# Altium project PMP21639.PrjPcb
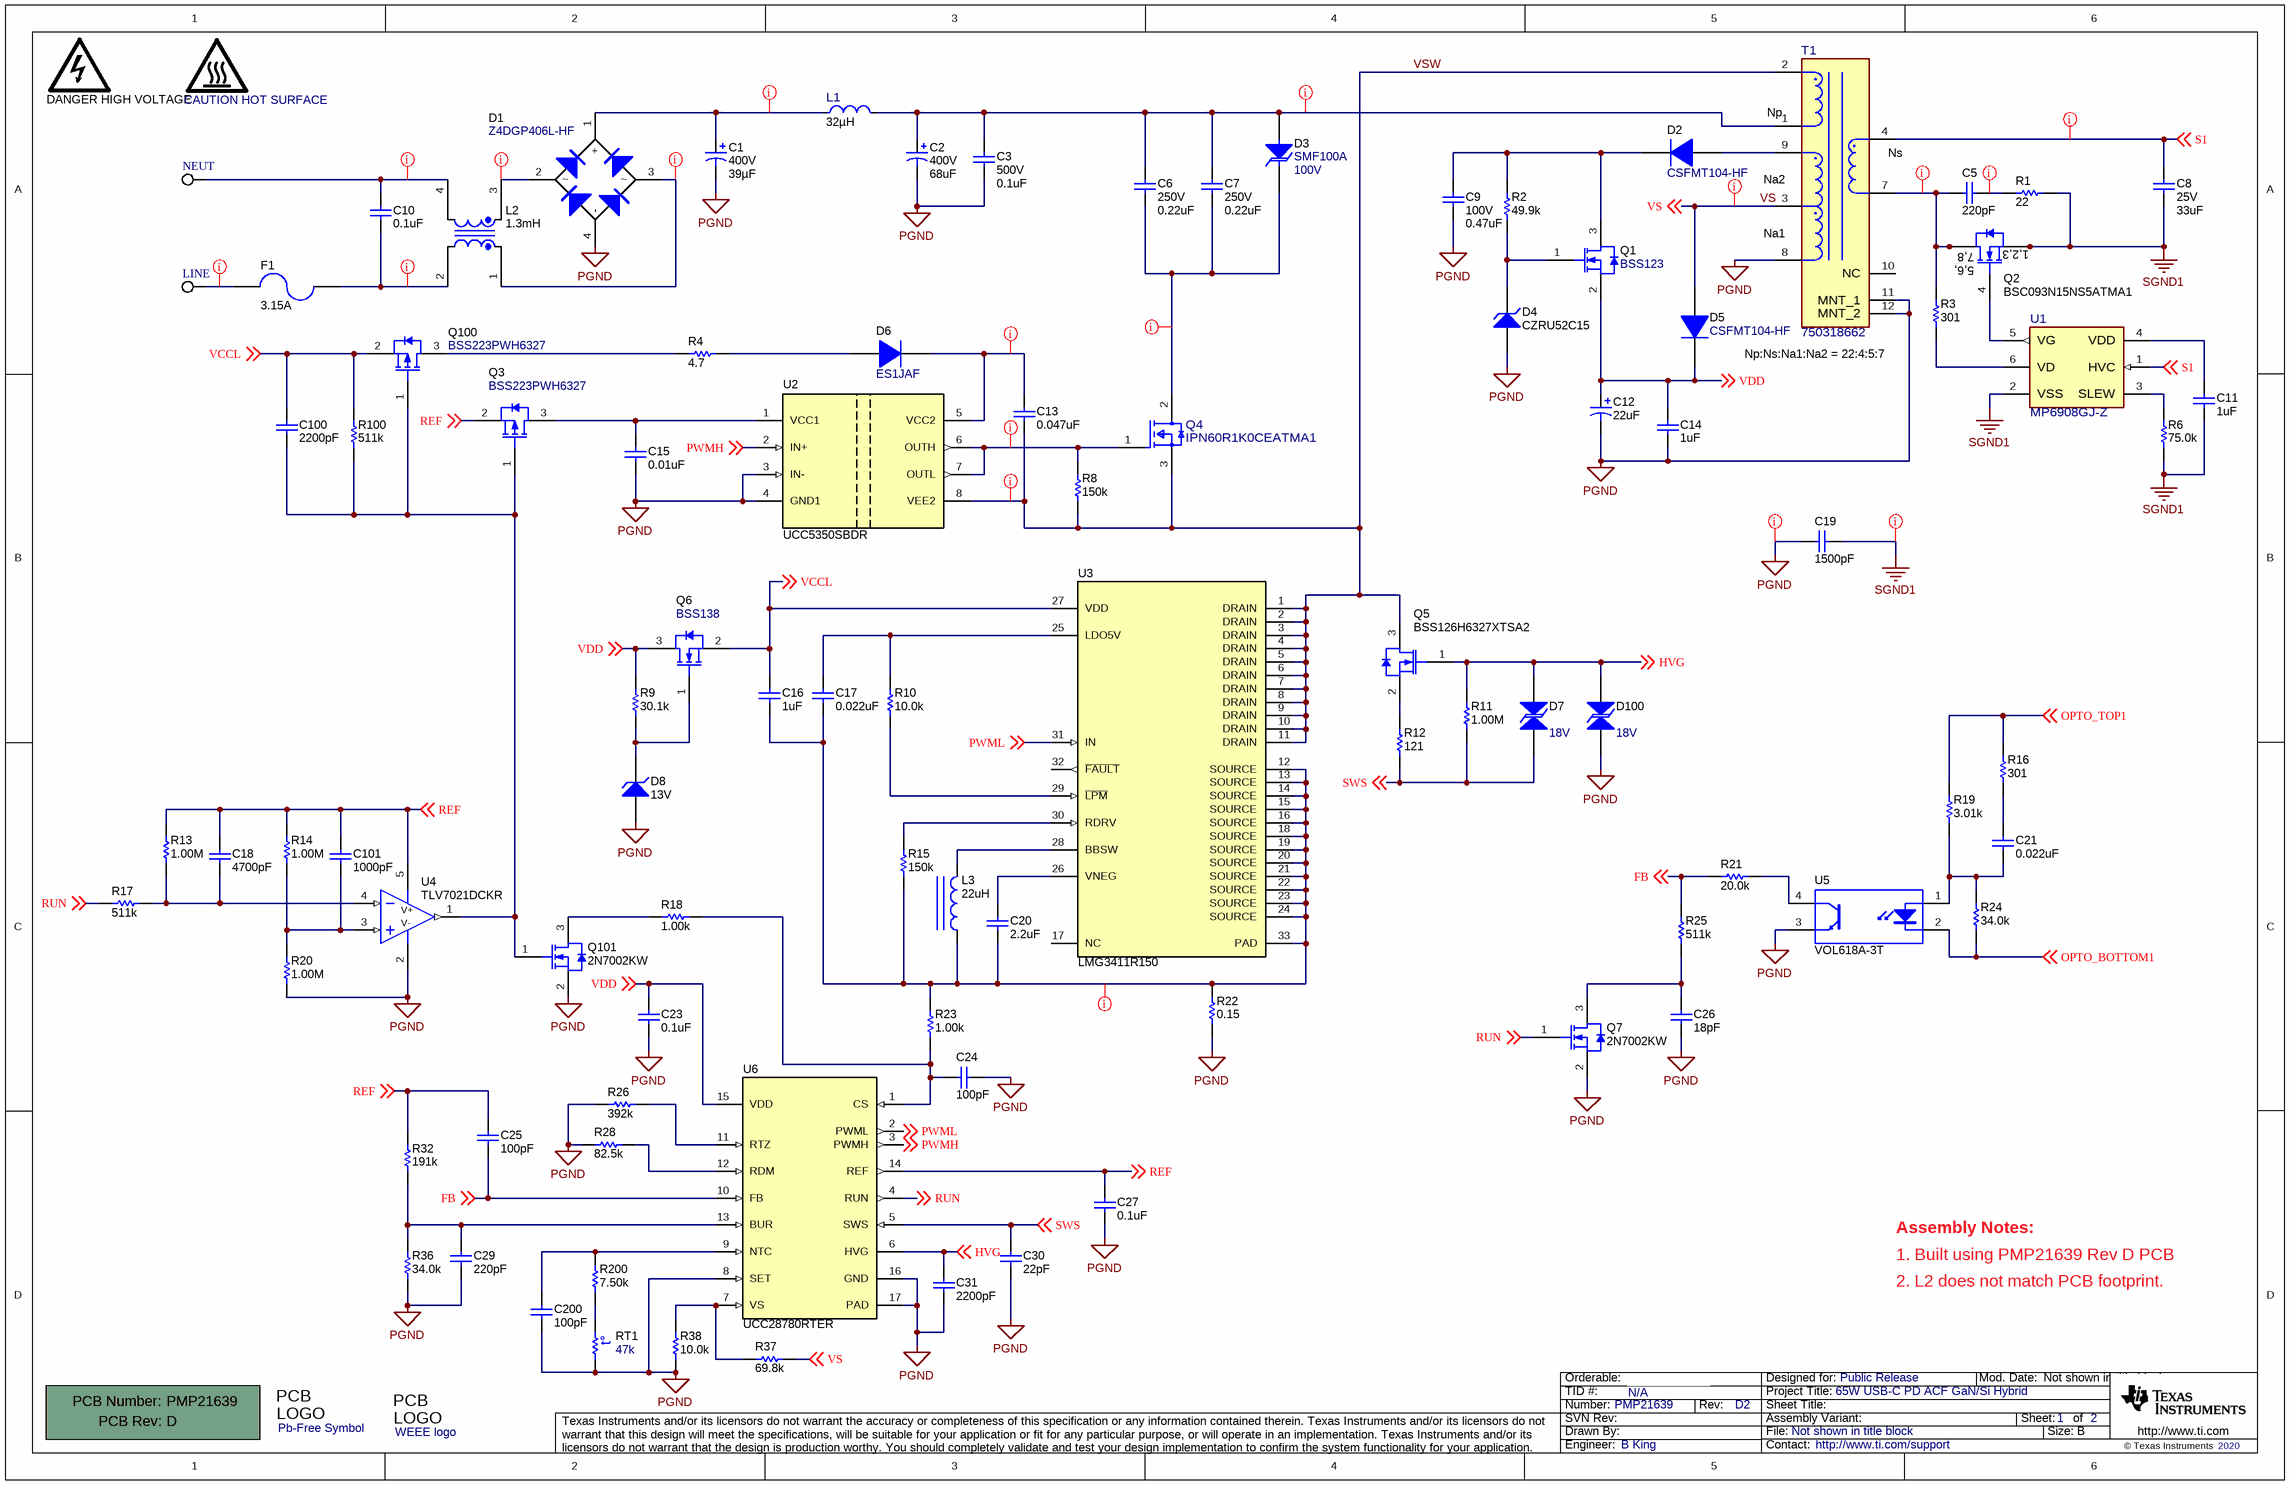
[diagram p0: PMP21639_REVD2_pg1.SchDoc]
TID: N/A; TechSupport: http://www.ti.com/support; SCH_Rev: D2; PRJ_Title: 65W USB-C PD ACF GaN/Si Hybrid; PRJ_Number: PMP21639; PRJ_Engineer: B King; PRJ_Customer: Public Release; PCB_Rev: D; PCB_Layout: B King; CopyrightYear: 2020
2 sheets, 123 parts. Net scope: global (net labels, ports and power ports of the same name join across sheets).
Board file: PMP21639_REVD_PCB.PcbDoc
Sheets:
  PMP21639_REVD2_pg1.SchDoc
  PMP21639_REVD2_pg2.SchDoc

## Sheet PMP21639_REVD2_pg1.SchDoc
size 431 x 279 mm; Date: Not shown in title block; ApprovedBy: Not shown in title block; CheckedBy: Not shown in title block; Author: Not shown in title block; CompanyName: Not shown in title block; Engineer: Not shown in title block; Organization: Not shown in title block; Address1: Not shown in title block; Address2: Not shown in title block; Address3: Not shown in title block; Address4: Not shown in title block; DocumentNumber: 1; Revision: Use project parameter SCH_Rev; SheetNumber: 1; SheetTotal: 2; PageSetup: Record=PageOptions¦CenterHorizontal=True¦CenterVertical=True¦PrintScale=0.48¦XCorrection=1.00¦YCorrection=1.00¦PrintKind=0¦BorderSize=5000000¦LeftOffset=0¦BottomOffset=0¦Orientation=2¦PaperLength=1000¦PaperWidth=1000¦Scale=100¦PaperSource=15¦PrintQuality=-3¦MediaType=1¦DitherType=10¦PrintScaleMode=1¦PaperKind=A5¦PaperIndex=11

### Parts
!PCB1  Printed Circuit Board  (value not drawn)  (mechanical)
C1  VDC_V: 400V  ValueDisplayed: 39µF  [Chemi-Con_1450x2000]  (hidden comment: EKXJ401ELL390MU20S)
C2  VDC_V: 400V  ValueDisplayed: 68uF  [BXW_1800x2000]  (hidden comment: 400BXW68MEFC18X20)
C3  VDC_V: 500V  ValueDisplayed: 0.1uF  [1210_230L]  (hidden comment: C1210W104KCRACTU)
C5  ValueDisplayed: 220pF  [0603S]  (hidden comment: C1608C0G2E221J080AA)
C6  VDC_V: 250V  ValueDisplayed: 0.22uF  [1206L]  (hidden comment: CGA5L3X7T2E224K160AE)
C7  VDC_V: 250V  ValueDisplayed: 0.22uF  [1206L]  (hidden comment: CGA5L3X7T2E224K160AE)
C8  VDC_V: 25V  ValueDisplayed: 33uF  [1206_180L]  (hidden comment: C3216X5R1E336M160AC)
C9  VDC_V: 100V  ValueDisplayed: 0.47uF  [1206_180]  (hidden comment: C3216X7R2A474K160AA)
C10  ValueDisplayed: 0.1uF  [CAPRR1000W60L1250T500H1100]  (hidden comment: BFC242042203)
C11  ValueDisplayed: 1uF  [0603S]  (hidden comment: GRM188R61E105KA12D)
C12  ValueDisplayed: 22uF  [Panasonic_500x1100]  (hidden comment: ECA1HM220)
C13  ValueDisplayed: 0.047uF  [0402S]  (hidden comment: GRM155R71E473KA88D)
C14  ValueDisplayed: 1uF  [0805L]  (hidden comment: C2012X7R1H105K085AC)
C15  ValueDisplayed: 0.01uF  [0402S]  (hidden comment: GRM155R71E103KA01D)
C16  ValueDisplayed: 1uF  [0603S]  (hidden comment: GRM188R61E105KA12D)
C17  ValueDisplayed: 0.022uF  [0402S]  (hidden comment: GRM155R71H223KA12D)
C18  ValueDisplayed: 4700pF  [0402S]  (hidden comment: GRM155R71C472KA01D)
C19  ValueDisplayed: 1500pF  [DK1_86]  (hidden comment: DK1E3EA152M86RAH01)
C20  ValueDisplayed: 2.2uF  [0805_150]  (hidden comment: 08053C225KAT2A)
C21  ValueDisplayed: 0.022uF  [0402S]  (hidden comment: GRM155R71H223KA12D)
C23  ValueDisplayed: 0.1uF  [0402S]  (hidden comment: GRM155R61H104ME14D)
C24  ValueDisplayed: 100pF  [0402S]  (hidden comment: GRM1555C1H101JA01D)
C25  ValueDisplayed: 100pF  [0402S]  (hidden comment: GRM1555C1H101JA01D)
C26  ValueDisplayed: 18pF  [0402S]  (hidden comment: GRM1555C1H180JA01D)
C27  ValueDisplayed: 0.1uF  [0402S]  (hidden comment: C1005X7R1H104K050BB)
C29  ValueDisplayed: 220pF  [0402S]  (hidden comment: C1005C0G1H221F050BA)
C30  ValueDisplayed: 22pF  [0402S]  (hidden comment: GRM1555C1H220FA01D)
C31  ValueDisplayed: 2200pF  [0402S]  (hidden comment: GRM155R71H222KA01D)
C100  ValueDisplayed: 2200pF  [0402S]  (hidden comment: GRM155R71H222KA01D)
C101  ValueDisplayed: 1000pF  [0402S]  (hidden comment: GRM155R71H102KA01D)
C200  ValueDisplayed: 100pF  [0402S]  (hidden comment: GRM1555C1H101JA01D)
D1  Z4DGP406L-HF  [Z4-D]
D2  CSFMT104-HF  [SOD-123H]
D3  SMF100A  value 100V  [SOD-123FL]
D4  CZRU52C15  [SOD-523F]
D5  CSFMT104-HF  [SOD-123H]
D6  ES1JAF  [SMAF]
D7  value 18V  [SOD-323-Bi]  (hidden comment: CDSOD323-T18C)
D8  13V  [SOD-323]
D100  value 18V  [SOD-323-Bi]  (hidden comment: CDSOD323-T18C)
F1  Irating_A: 3.15A  [FUSE_392]  (hidden comment: 39213150000)
L1  Ind_H: 32µH  [FP-7447052_PTH_D10MM0-MFG]  (hidden comment: 7447052)
L2  ValueDisplayed: 1.3mH  [Renco_RLTI-1301]  (hidden comment: 7448201036010)
L3  ValueDisplayed: 22uH  [1007]  (hidden comment: BRC2518T220K)
LINE  5012  [Keystone5012]  (value not drawn)
LOGO1  DANGER HIGH VOLTAGE  [IEC_HighVoltage_Small]  (no BOM)
Logo2  Pb-Free Symbol  [Pb-Free_Overlay_Medium]  (no BOM)
Logo3  WEEE logo  [WEEE_Minimum]  (no BOM)
LOGO4  CAUTION HOT SURFACE  [IEC_HotSurface_Small]  (no BOM)
NEUT  5012  [Keystone5012]  (value not drawn)
Q1  BSS123  [SOT-23L]
Q2  BSC093N15NS5ATMA1  [PG-TDSON-8]
Q3  BSS223PWH6327  [SOT-323]
Q4  IPN60R1K0CEATMA1  [FP-IPN60R1K0CEATMA1_SOT223-3-MFG]
Q5  BSS126H6327XTSA2  [SOT-23L]
Q6  BSS138  [SOT-23]
Q7  2N7002KW  [SOT-323]
Q100  BSS223PWH6327  [SOT-323]
Q101  2N7002KW  [SOT-323]
R1  ValueDisplayed: 22  [0805L]  (hidden comment: CRCW080522R0JNEA)
R2  ValueDisplayed: 49.9k  [0402S]  (hidden comment: CRCW040249K9FKED)
R3  ValueDisplayed: 301  [0402S]  (hidden comment: CRCW0402301RFKED)
R4  ValueDisplayed: 4.7  [0402S]  (hidden comment: CRCW04024R70JNED)
R6  ValueDisplayed: 75.0k  [0402S]  (hidden comment: CRCW040275K0FKED)
R8  ValueDisplayed: 150k  [0402S]  (hidden comment: ERJ-2RKF1503X)
R9  ValueDisplayed: 30.1k  [0402S]  (hidden comment: RC0402FR-0730K1L)
R10  ValueDisplayed: 10.0k  [0402S]  (hidden comment: RC0402FR-0710KL)
R11  ValueDisplayed: 1.00M  [0402S]  (hidden comment: RC0402FR-071ML)
R12  ValueDisplayed: 121  [0402S]  (hidden comment: CRCW0402121RFKED)
R13  ValueDisplayed: 1.00M  [0402S]  (hidden comment: CRCW04021M00FKED)
R14  ValueDisplayed: 1.00M  [0402S]  (hidden comment: CRCW04021M00FKED)
R15  ValueDisplayed: 150k  [0402S]  (hidden comment: ERJ-2RKF1503X)
R16  ValueDisplayed: 301  [0402]  (hidden comment: CRCW0402301RFKED)
R17  ValueDisplayed: 511k  [0402S]  (hidden comment: CRCW0402511KFKED)
R18  ValueDisplayed: 1.00k  [0402S]  (hidden comment: CRCW04021K00FKED)
R19  ValueDisplayed: 3.01k  [0402]  (hidden comment: CRCW04023K01FKED)
R20  ValueDisplayed: 1.00M  [0402S]  (hidden comment: CRCW04021M00FKED)
R21  ValueDisplayed: 20.0k  [0402S]  (hidden comment: CRCW040220K0FKED)
R22  ValueDisplayed: 0.15  [1206L]  (hidden comment: ERJ-8BSFR15V)
R23  ValueDisplayed: 1.00k  [0402S]  (hidden comment: CRCW04021K00FKED)
R24  ValueDisplayed: 34.0k  [0402S]  (hidden comment: CRCW040234K0FKED)
R25  ValueDisplayed: 511k  [0402S]  (hidden comment: CRCW0402511KFKED)
R26  ValueDisplayed: 392k  [0402S]  (hidden comment: CRCW0402383KFKED)
R28  ValueDisplayed: 82.5k  [0402S]  (hidden comment: CRCW040282K5FKED)
R32  ValueDisplayed: 191k  [0402S]  (hidden comment: CRCW0402191KFKED)
R36  ValueDisplayed: 34.0k  [0402S]  (hidden comment: CRCW040234K0FKED)
R37  ValueDisplayed: 69.8k  [0402S]  (hidden comment: CRCW040269K8FKED)
R38  ValueDisplayed: 10.0k  [0402S]  (hidden comment: ERJ-2RKF1002X)
R100  ValueDisplayed: 511k  [0402S]  (hidden comment: CRCW0402511KFKED)
R200  ValueDisplayed: 7.50k  [0402S]  (hidden comment: CRCW04027K50FKED)
RT1  value 47k  [0603S]  (hidden comment: NCP18WB473J03RB)
T1  750318662  [FP-750318555_PTH_TRANSFORMER_24MM64_24MM64-MFG]
U1  MP6908GJ-Z  [FP-MP6908GJ-Z_TSOT23-6-MFG]
U2  UCC5350SBDR  [D0008B_L]
U3  PartNumber: LMG3411R150  [RWH0032A]  (hidden comment: LMG3411R150RWHR)
U4  TLV7021DCKR  [DCK0005A_L]
U5  VOL618A-3T  [SOP254P1020X230-4]
U6  UCC28780RTER  [RTE0016C_NV]

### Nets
PGND: C1.2(-) C2.2(-) C3.2 C9.1 C12.2(-) C14.1 C15.2 C19.2 C23.2 C24.1 C26.2 C27.2 C29.2 C30.2 C31.2 C200.1 D1.4(-) D4.2(A) D8.2(A) D100.1 Q7.2(S) Q101.2(S) R20.1 R22.1 R26.1 R28.2 R36.1 R38.1 RT1.1 T1.8 T1.11(MNT_1) T1.12(MNT_2) U2.3(IN-) U2.4(GND1) U4.2(V-) U5.3(E) U6.8(SET) U6.16(GND) U6.17(PAD)
SGND1: C8.2 C11.2 C19.1 Q2.1(S) Q2.2(S) Q2.3(S) R1.2 R6.2 U1.2(VSS)
FB: C25.1 R21.1 R25.2 U6.10(FB) ; off-sheet FB
HVG: C31.1 D7.2 D100.2 Q5.1(G) R11.2 U6.6(HVG) ; off-sheet HVG
OPTO_BOTTOM1: R24.1 U5.2(K) ; off-sheet OPTO_BOTTOM1
OPTO_TOP1: R16.2 R19.1 ; off-sheet OPTO_TOP1
PWMH: U2.2(IN+) U6.3(PWMH) ; off-sheet PWMH
PWML: U3.31(IN) U6.2(PWML) ; off-sheet PWML
REF: C18.1 C25.2 C27.1 C101.1 Q3.2(S) R13.2 R14.2 R32.1 U4.5(V+) U6.14(REF) ; off-sheet REF
RUN: Q7.1(G) R17.2 U6.4(RUN) ; off-sheet RUN
S1: C8.1 T1.4 U1.1(HVC) ; off-sheet S1
SWS: C30.1 D7.1 R11.1 R12.1 U6.5(SWS) ; off-sheet SWS
VCCL: C16.1 C100.1 Q6.2(S) Q100.2(S) R100.2 U3.27(VDD) ; off-sheet VCCL
VDD: C12.1(+) C14.2 C23.1 D5.1(K) Q1.2(S) Q6.3(D) R9.2 U6.15(VDD) ; off-sheet VDD
VS: D5.2(A) R37.1 T1.3 ; off-sheet VS
VSW: C13.2 Q4.3(Source) Q5.3(D) R8.1 T1.2 U2.8(VEE2) U3.1(DRAIN) U3.2(DRAIN) U3.3(DRAIN) U3.4(DRAIN) U3.5(DRAIN) U3.6(DRAIN) U3.7(DRAIN) U3.8(DRAIN) U3.9(DRAIN) U3.10(DRAIN) U3.11(DRAIN)
NetC1_1: C1.1(+) D1.1(+) L1.1
NetC2_1: C2.1(+) C3.1 C6.1 C7.1 D3.2(A) L1.2 T1.1
NetC5_1: C5.1 R1.1
NetC5_2: C5.2 Q2.5(D) Q2.6(D) Q2.7(D) Q2.8(D) Q2.9(D) R3.2 T1.7
NetC6_2: C6.2 C7.2 D3.1(K) Q4.2(Drain)
NetC9_2: C9.2 D2.1(K) Q1.3(D) R2.1
NetC10_1: C10.1 L2.4 NEUT.1
NetC10_2: C10.2 F1.1 L2.2
NetC11_1: C11.1 U1.4(VDD)
NetC13_1: C13.1 D6.1(K) U2.5(VCC2)
NetC15_1: C15.1 Q3.3(D) U2.1(VCC1)
NetC16_2: C16.2 C17.1 C20.2 L3.1 R15.1 R22.2 R23.2 U3.12(SOURCE) U3.13(SOURCE) U3.14(SOURCE) U3.15(SOURCE) U3.16(SOURCE) U3.18(SOURCE) U3.19(SOURCE) U3.20(SOURCE) U3.21(SOURCE) U3.22(SOURCE) U3.23(SOURCE) U3.24(SOURCE) U3.33(PAD)
NetC17_2: C17.2 R10.2 U3.25(LDO5V)
NetC18_2: C18.2 R13.1 R17.1 U4.4(IN-)
NetC20_1: C20.1 U3.26(VNEG)
NetC21_1: C21.1 R19.2 R24.2 U5.1(A)
NetC21_2: C21.2 R16.1
NetC24_2: C24.2 R18.1 R23.1 U6.1(CS)
NetC26_1: C26.1 Q7.3(D) R25.1
NetC29_1: C29.1 R32.2 R36.2 U6.13(BUR)
NetC100_2: C100.2 Q3.1(G) Q100.1(G) Q101.1(G) R100.1 U4.1(OUT)
NetC101_2: C101.2 R14.1 R20.2 U4.3(IN+)
NetC200_2: C200.2 R200.2 U6.9(NTC)
NetD1_2: D1.2 L2.3
NetD1_3: D1.3 L2.1
NetD2_2: D2.2(A) T1.9
NetD4_1: D4.1(K) Q1.1(G) R2.2
NetD6_2: D6.2(A) R4.2
NetD8_1: D8.1(K) Q6.1(G) R9.1
NetF1_2: F1.2 LINE.1
NetL3_2: L3.2 U3.28(BBSW)
NetQ2_4: Q2.4(G) U1.5(VG)
NetQ4_1: Q4.1(Gate) R8.2 U2.6(OUTH) U2.7(OUTL)
NetQ5_2: Q5.2(S) R12.2
NetQ100_3: Q100.3(D) R4.1
NetQ101_3: Q101.3(D) R18.2
NetR3_1: R3.1 U1.6(VD)
NetR6_1: R6.1 U1.3(SLEW)
NetR10_1: R10.1 U3.29(~{LPM})
NetR15_2: R15.2 U3.30(RDRV)
NetR21_2: R21.2 U5.4(C)
NetR26_2: R26.2 U6.11(RTZ)
NetR28_1: R28.1 U6.12(RDM)
NetR37_2: R37.2 R38.2 U6.7(VS)
NetR200_1: R200.1 RT1.2

Not connected (* = marked no-connect by the designer): T1 10(NC); U3 17(NC) 32(~{FAULT})

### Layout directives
net class PGND: NetC16_2, PGND, VS
net class High Voltage: NetC1_1, NetC2_1, NetC6_2
net class SGND: NetC5_1, NetC5_2, S1, SGND1
net class Switch Node: NetC13_1, NetQ4_1, VSW
net class VAC: NetC10_1, NetC10_2, NetD1_2, NetD1_3, NetF1_2

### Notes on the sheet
- (near T1) Np
- (near T1) Ns
- (near T1) Na1
- (near T1) Na2
- Np:Ns:Na1:Na2 = 22:4:5:7
- Assembly Notes:
- 1. Built using PMP21639 Rev D PCB
- 2. L2 does not match PCB footprint.

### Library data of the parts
!PCB1 = PCB: Manufacturer: Any; PartNumber: PMP21639; SymbolCreator: a0412235
C1 = CMP-0067531-1: CAP, AL, 39 µF, 400 V, +/- 20%, AEC-Q200 Grade 2, TH; Manufacturer: Chemi-Con; TaMin_C: -40°C; Polarized: Y; SizeAreaWB_mm2: 272.25; Value1: Unknown; U/M: EA; Value: 39uF; TaMax_C: 105°C; SizeZ_mm: 21.5; SizeX_mm: 14.5; Cap_Case: 14.5X20mm; SizeArea_mm2: 210.25; CompType: Capacitor; IRMS_A: 385mA; AEC Grade: 2; AEC Category: Q200
C2 = CMP-0009972-1: CAP, AL, 68 uF, 400 V, +/- 20%, TH; Manufacturer: Rubycon; PartNumber: 400BXW68MEFR18X20; TaMin_C: -40°C; Polarized: Y; SizeAreaWB_mm2: 400; Value1: Unknown; U/M: EA; Value: 68uF; TaMax_C: 105°C; SizeZ_mm: 22; SizeX_mm: 18; Cap_Case: 18x20mm; SizeArea_mm2: 324; CompType: Capacitor; AEC Qualified: N; Cap_F: 68µF; IRMS_A: 530mA; AEC Category: Q200
C3 = CMP-0009094-1: CAP, CERM, 0.1 uF, 500 V, +/- 10%, X7R, 1210; Manufacturer: Kemet; TaMin_C: -55°C; Polarized: N; SizeAreaWB_mm2: 14.7; Value1: Unknown; U/M: EA; Value: 0.1uF; TaMax_C: 125°C; SizeZ_mm: 2.3; SizeX_mm: 3.2; SizeY_mm: 2.5; Cap_Case: 1210; SizeArea_mm2: 8; Cap_F: 100nF; AEC Category: Q200
C5 = CMP-0006996-4: CAP, CERM, 220 pF, 250 V, +/- 5%, C0G/NP0, 0603; Manufacturer: TDK; TaMin_C: -55°C; Polarized: N; SizeAreaWB_mm2: 4.68; Value1: Unknown; U/M: EA; Value: 220pF; TaMax_C: 125°C; SizeZ_mm: 1; SizeX_mm: 1.6; SizeY_mm: 0.8; Cap_Case: 0603; Value2: 250V; SizeArea_mm2: 1.28; CompType: Capacitor; AEC Category: Q200
C6 C7 = CMP-0008793-2: CAP, CERM, 0.22 uF, 250 V, +/- 10%, X7T, AEC-Q200 Grade 1, 1206; Manufacturer: TDK; TaMin_C: -55°C; Polarized: N; SizeAreaWB_mm2: 10.92; Value1: Unknown; U/M: EA; Value: 0.22uF; TaMax_C: 125°C; SizeZ_mm: 1.35; SizeX_mm: 3.2; SizeY_mm: 1.6; Cap_Case: 1206; SizeArea_mm2: 5.12; CompType: Capacitor; AEC Qualified: Y; Cap_F: 220nF; AEC Grade: 1; AEC Category: Q200
C8 = CMP-0008655-2: CAP, CERM, 33 uF, 25 V, +/- 20%, X5R, 1206; Manufacturer: TDK; TaMin_C: -55°C; ESR_ohm: 2.648m; Polarized: N; SizeAreaWB_mm2: 10.92; Value1: 0.002648 ohm; U/M: EA; Value: 33uF; TaMax_C: 85°C; SizeZ_mm: 1.8; SizeX_mm: 3.2; SizeY_mm: 1.6; Cap_Case: 1206_180; SizeArea_mm2: 5.12; CompType: Capacitor; Cap_F: 33µF; IRMS_A: 4.45864A; AEC Category: Q200
C9 = CMP-0008716-2: CAP, CERM, 0.47 uF, 100 V, +/- 10%, X7R, 1206; Manufacturer: TDK; TaMin_C: -55°C; ESR_ohm: 7.558m; Polarized: N; SizeAreaWB_mm2: 10.92; Value1: 0.007558 ohm; U/M: EA; Value: 0.47uF; TaMax_C: 125°C; SizeZ_mm: 1.8; SizeX_mm: 3.2; SizeY_mm: 1.6; SizeArea_mm2: 5.12; Cap_F: 470nF; IRMS_A: 2.64716A; AEC Category: Q200
C10 = CMP-0012470-3: CAP, Film, 0.1 uF, 275V X2; Manufacturer: Kemet; PartNumber: R46KF3100DQP1M; TaMin_C: -55°C; Polarized: N; Value1: Unknown; Value: 0.1uF; TaMax_C: 85°C; Tolerance_%: 2%; Cap_Case: Radial 12.5x5.5x11; Value2: 630V; Cap_F: 22nF; AEC Category: Q200
C11 C16 = CMP-0007343-5: CAP, CERM, 1 uF, 25 V, +/- 10%, X5R, 0603; Manufacturer: MuRata; TaMin_C: -55°C; Polarized: N; SizeAreaWB_mm2: 4.68; Value1: Unknown; U/M: EA; Value: 1uF; TaMax_C: 85°C; SizeZ_mm: 1; SizeX_mm: 1.6; SizeY_mm: 0.8; Cap_Case: 0603; Value2: 25V; SizeArea_mm2: 1.28; CompType: Capacitor; Cap_F: 1µF; AEC Category: Q200
C12 = CMP-0064895-2: CAP, AL, 22 uF, 50 V, +/- 20%, TH; Manufacturer: Panasonic; TaMin_C: -40°C; Polarized: Y; SizeAreaWB_mm2: 49; Value1: Unknown; U/M: EA; Value: 22uF; TaMax_C: 85°C; SizeZ_mm: 12.5; SizeX_mm: 5; Cap_Case: 5x11; Value2: 50V; SizeArea_mm2: 25; CompType: Capacitor; AEC Qualified: N; Cap_F: 22µF; AEC Category: Q200
C13 = CMP-0006669-2: CAP, CERM, 0.047 uF, 25 V, +/- 10%, X7R, 0402; Manufacturer: MuRata; TaMin_C: -55°C; Polarized: N; SizeAreaWB_mm2: 3; Value1: Unknown; U/M: EA; TaMax_C: 125°C; SizeZ_mm: 0.6; SizeX_mm: 1; SizeY_mm: 0.5; Cap_Case: 0402; Value2: 25V; Cap_F: 47nF; AEC Category: Q200
C14 = CMP-0007872-2: CAP, CERM, 1 uF, 50 V, +/- 10%, X7R, 0805; Manufacturer: TDK; TaMin_C: -55°C; Polarized: N; SizeAreaWB_mm2: 6.75; Value1: Unknown; U/M: EA; Value: 1uF; TaMax_C: 125°C; SizeZ_mm: 1.45; SizeX_mm: 2; SizeY_mm: 1.25; Cap_Case: 0805; Value2: 50V; SizeArea_mm2: 2.5; CompType: Capacitor; Cap_F: 1µF; AEC Category: Q200
C15 = CMP-0006658-2: CAP, CERM, 0.01 uF, 25 V, +/- 10%, X7R, 0402; Manufacturer: MuRata; TaMin_C: -55°C; Polarized: N; SizeAreaWB_mm2: 3; Value1: Unknown; U/M: EA; Value: 0.01uF; TaMax_C: 125°C; SizeZ_mm: 0.6; SizeX_mm: 1; SizeY_mm: 0.5; Cap_Case: 0402; Value2: 25V; CompType: Capacitor; Cap_F: 10nF; AEC Category: Q200
C17 C21 = CMP-0006684-2: CAP, CERM, 0.022 uF, 50 V, +/- 10%, X7R, 0402; Manufacturer: MuRata; TaMin_C: -55°C; Polarized: N; SizeAreaWB_mm2: 3; Value1: Unknown; U/M: EA; TaMax_C: 125°C; SizeZ_mm: 0.6; SizeX_mm: 1; SizeY_mm: 0.5; Cap_Case: 0402; Value2: 50V; CompType: Capacitor; Cap_F: 22nF; AEC Category: Q200
C18 = CMP-0006652-2: CAP, CERM, 4700 pF, 16 V, +/- 10%, X7R, 0402; Manufacturer: MuRata; TaMin_C: -55°C; Polarized: N; SizeAreaWB_mm2: 3; Value1: Unknown; U/M: EA; Value: 4700pF; TaMax_C: 125°C; SizeZ_mm: 0.6; SizeX_mm: 1; SizeY_mm: 0.5; Cap_Case: 0402; Value2: 16V; Cap_F: 4.7nF; AEC Category: Q200
C19 = CMP-0077998-1: CAP, CERM, 1500 pF, X1 440 VAC/Y1 250 VAC, +/- 20%, E, 8x6mm; Manufacturer: MuRata; Cap_F: 1.5nF; SizeAreaWB_mm2: 107.2; VAC_X: 440; VAC_Y: 250; SizeArea_mm2: 68.4; AEC Qualified: N; AEC Category: Q200; Value: 1500pF; TaMax_C: 125°C; SizeZ_mm: 2.5; TaMin_C: -40°C; SizeY_mm: 6; U/M: EA; AC_Safety: X1Y1; CompType: Capacitor; SizeX_mm: 11.4
C20 = CMP-0007573-2: CAP, CERM, 2.2 uF, 25 V, +/- 10%, X7R, 0805; Manufacturer: AVX; TaMin_C: -55°C; Polarized: N; SizeAreaWB_mm2: 6.75; Value1: Unknown; U/M: EA; Value: 2.2uF; TaMax_C: 125°C; SizeZ_mm: 1.5; SizeX_mm: 2; SizeY_mm: 1.25; Cap_Case: 0805; Value2: 25V; SizeArea_mm2: 2.5; CompType: Capacitor; Cap_F: 2.2µF; AEC Category: Q200
C23 = CMP-0006614-2: CAP, CERM, 0.1 uF, 50 V, +/- 20%, X5R, 0402; Manufacturer: MuRata; TaMin_C: -55°C; Polarized: N; SizeAreaWB_mm2: 3; Value1: Unknown; U/M: EA; Value: 0.1uF; TaMax_C: 85°C; SizeZ_mm: 0.6; SizeX_mm: 1; SizeY_mm: 0.5; Cap_Case: 0402; Value2: 50V; CompType: Capacitor; Cap_F: 100nF; AEC Category: Q200
C24 C25 C200 = CMP-0006410-2: CAP, CERM, 100 pF, 50 V, +/- 5%, C0G/NP0, 0402; Manufacturer: MuRata; TaMin_C: -55°C; Polarized: N; SizeAreaWB_mm2: 3; Value1: Unknown; U/M: EA; Value: 100pF; TaMax_C: 125°C; SizeZ_mm: 0.6; SizeX_mm: 1; SizeY_mm: 0.5; Cap_Case: 0402; Value2: 50V; AEC Category: Q200
C26 = CMP-0006424-2: CAP, CERM, 18 pF, 50 V, +/- 5%, C0G/NP0, 0402; Manufacturer: MuRata; TaMin_C: -55°C; Polarized: N; SizeAreaWB_mm2: 3; Value1: Unknown; U/M: EA; Value: 18pF; SizeZ_mm: 0.6; SizeX_mm: 1; SizeY_mm: 0.5; Cap_Case: 0402; Value2: 50V; TaMax_C: 125°C; AEC Category: Q200
C27 = CMP-0006297-2: CAP, CERM, 0.1 uF, 50 V, +/- 10%, X7R, 0402; Manufacturer: TDK; TaMin_C: -55°C; ESR_ohm: 0.039064; Polarized: N; SizeAreaWB_mm2: 3; Value1: 0.039064 ohm; U/M: EA; Value: 0.1uF; TaMax_C: 125°C; SizeZ_mm: 0.6; SizeX_mm: 1; SizeY_mm: 0.5; Cap_Case: 0402; Value2: 50V; CompType: Capacitor; Cap_F: 100nF; IRMS_A: 8.14669dA; AEC Category: Q200
C29 = CMP-0006249-2: CAP, CERM, 220 pF, 50 V, +/- 1%, C0G/NP0, 0402; Manufacturer: TDK; TaMin_C: -55°C; Polarized: N; SizeAreaWB_mm2: 3; Value1: Unknown; U/M: EA; Value: 220pF; TaMax_C: 125°C; SizeZ_mm: 0.6; SizeX_mm: 1; SizeY_mm: 0.5; Cap_Case: 0402; Value2: 50V; CompType: Capacitor; AEC Category: Q200
C30 = CMP-0006438-2: CAP, CERM, 22 pF, 50 V, +/- 1%, C0G/NP0, 0402; Manufacturer: MuRata; TaMin_C: -55°C; Polarized: N; SizeAreaWB_mm2: 3; Value1: Unknown; U/M: EA; Value: 22pF; TaMax_C: 125°C; SizeZ_mm: 0.6; SizeX_mm: 1; SizeY_mm: 0.5; Cap_Case: 0402; Value2: 50V; CompType: Capacitor; AEC Category: Q200
C31 C100 = CMP-0006683-2: CAP, CERM, 2200 pF, 50 V, +/- 10%, X7R, 0402; Manufacturer: MuRata; TaMin_C: -55°C; Polarized: N; SizeAreaWB_mm2: 3; Value1: Unknown; U/M: EA; Value: 2200pF; TaMax_C: 125°C; SizeZ_mm: 0.6; SizeX_mm: 1; SizeY_mm: 0.5; Cap_Case: 0402; Value2: 50V; CompType: Capacitor; Cap_F: 2.2nF; AEC Category: Q200
C101 = CMP-0006673-2: CAP, CERM, 1000 pF, 50 V, +/- 10%, X7R, 0402; Manufacturer: MuRata; TaMin_C: -55°C; Polarized: N; SizeAreaWB_mm2: 3; Value1: Unknown; U/M: EA; Value: 1000pF; TaMax_C: 125°C; SizeZ_mm: 0.6; SizeX_mm: 1; SizeY_mm: 0.5; Cap_Case: 0402; Value2: 50V; Cap_F: 1nF; AEC Category: Q200
D1 = CMP-0029244-3: Diode, P-N-Bridge, 600 V, 4 A, Z4-D; Manufacturer: Comchip Technology; Value1: 4A; SizeZ_mm: 1.55; Value: 600V; SizeArea_mm2: 85.05; SizeY_mm: 8.1; SizeAreaWB_mm2: 126.25; Value2: 0.95V; Green_REACh: Incomplete; TJmax_C: 175°C; Green_Lifecycle: Not Set; Vf_V: 950mV; AEC Qualified: N; AEC Category: Q101; SizeX_mm: 10.5
D2 D5 = CMP-0029199-2: Diode, Superfast Rectifier, 200 V, 1 A, 3.5x1.6mm; Manufacturer: Comchip Technology; Value2: 0.95V; SizeX_mm: 3.5; SizeAreaWB_mm2: 11.7; SizeZ_mm: 1; SizeArea_mm2: 5.6; Vf_V: 950mV; SizeY_mm: 1.6; Value1: 1A; AEC Qualified: N; AEC Category: Q101; Value: 200V; TJmax_C: 150°C
D3 = CMP-0005818-4: Diode, TVS, Uni, 100V, SOD-123FL; PartNumber: SMF100A-T13; Manufacturer: Littelfuse; SizeX_mm: 3.6; VRWM: 36V; Vc: 58.1V; SizeZ_mm: 0.98; Ppk: 200W; AEC Category: Q101; Vbr_Min: 40V; SizeAreaWB_mm2: 12.19; Ipp: 3.4A; SizeArea_mm2: 5.94; SizeY_mm: 1.65; RJA_CperW: 220; Vbr_Max: 44.2V
D4 = CMP-0080806-3: Diode, Zener, 15 V, 150 mW, SOD-523F; Manufacturer: Comchip Technology; SizeY_mm: 0.9; SizeAreaWB_mm2: 5.13; Value1: 0.15W; Power_W: 150mW; Value: 15V; AEC Qualified: N; SizeZ_mm: 0.85; AEC Category: Q101; SizeArea_mm2: 1.53; SizeX_mm: 1.7
D6 = CMP-0029162-1: Diode, Ultrafast, 600 V, 1 A, AEC-Q101, SMAF; Manufacturer: Fairchild Semiconductor; Io_A: 1A; Green_Lifecycle: Not Set; SizeAreaWB_mm2: 19.95; Vr_V: 600V; Green_REACh: Incomplete; TJmax_C: 150°C; U/M: EA; Value: 600V; SizeZ_mm: 1; SizeX_mm: 4.7; SizeY_mm: 2.5; Vf_V: 1.7V; SizeArea_mm2: 11.75; AEC Qualified: Y; AEC Category: Q101
D7 D100 = CMP-0005822-3: Diode, TVS, Bi, 18 V, SOD-323; Manufacturer: Bourns; SizeArea_mm2: 3.645; SizeY_mm: 1.35; VRWM: 24V; Ppk: 350W; SizeZ_mm: 1; SizeX_mm: 2.7; SizeAreaWB_mm2: 8.695; AEC Category: Q101
D8 = CMP-0005832-2: Diode, Zener, 13 V, 200 mW, SOD-323; Manufacturer: Diodes Inc.; PartNumber: MMSZ5243BS-7-F; Value1: 0.2W; RJA_CperW: 350; U/M: EA; SizeZ_mm: 1; SizeX_mm: 2.7; SizeY_mm: 1.35; SizeArea_mm2: 3.645; AEC Category: Q101; Power_W: 200mW; SizeAreaWB_mm2: 8.695
F1 = CMP-0003561-1: Fuse, 3.15 A, 250VAC/VDC, TH; Manufacturer: Littelfuse; VAC_V: 250V
L1 = CMP-0087546-1: WE-FI Leaded Toroidal Line Choke; Manufacturer: Wurth; SizeZ_mm: 10mm; Irms: 2.6A; DCR_ohm: 0.045; AEC Qualified: No; Symbol Name: SYM-7447052
L2 = CMP-0086351-1: Coupled inductor, 1.3 mH, 0.035 ohm, TH; Manufacturer: Wurth; SizeY_mm: 15.24; DCR_ohm: 0.035; AEC Category: Q200; AEC Qualified: N; SizeX_mm: 9.906; Value: 1.3mH; SizeAreaWB_mm2: 205.25944; SizeZ_mm: 18.415; SizeArea_mm2: 150.96744
L3 = CMP-0060002-2: Inductor, Wirewound, 22 uH, 0.49 A, 0.56 ohm, SMD; Manufacturer: Taiyo Yuden; Isat: 0.64A @ 30% inductance drop; Irms: 0.49A @ 40C rise; Green_Lifecycle: Active; SizeAreaWB_mm2: 9.8; DCR_ohm: 5.6d; Green_REACh: Passed; Value: 22uH; Imax_A: 4.9dA; SizeZ_mm: 2; SizeX_mm: 2.5; SizeY_mm: 1.8; Value2: 0.49A; SizeArea_mm2: 4.5; Ind_H: 22µH; AEC Qualified: N; AEC Category: Q200
LINE NEUT = CMP-0055149-1: Test Point, Multipurpose, White, TH; Manufacturer: Keystone; CNHeader: FALSE; Green_Lifecycle: Active; Green_REACh: Passed; ContactFinish: Silver; CT: TRUE
LOGO1 = IEC_HighVoltage: IEC 61010-1 High Voltage Warning; SymbolCreator: a0412235
Logo2 = CMP-0074839-1: SymbolCreator: a0412235
Logo3 = CMP-0074769-1
LOGO4 = CMP-0074837-1: IEC 61010-1 Hot Surface Warning; SymbolCreator: a0412235
Q1 = CMP-0000947-1: MOSFET, N-CH, 100 V, 0.17 A, SOT-23; Alternate Manufacturer: None; Manufacturer: Fairchild Semiconductor; SizeZ_mm: 1.1; ChType: N; Value2: 1.8 nC; Value1: 1; VdsMax_V: 100V; SizeX_mm: 2.5; SizeY_mm: 3; Vgs_V: 20V; Value: 100V; Rdson45_ohm: 10; SizeArea_mm2: 7.5; AEC Category: Q101; IdsMax_A: 170mA; SizeAreaWB_mm2: 14; U/M: EA; QgTyp_nC: 1.8
Q2 = CMP-0001046-2: MOSFET, N-CH, 150 V, 87 A, PG-TDSON-8; Alternate Manufacturer: None; Manufacturer: Infineon Technologies; SizeZ_mm: 1.12; ChType: N; Value2: 33 nC; VdsMax_V: 150V; SizeX_mm: 5.99; SizeY_mm: 4.9; Vgs_V: 20V; QgTyp_nC: 33; Value: 150V; SizeArea_mm2: 29.351; AEC Category: Q101; IdsMax_A: 87A; SizeAreaWB_mm2: 55.131; U/M: EA
Q3 Q100 = CMP-0000010-3: MOSFET, P-CH, -20 V, -0.39 A, SOT-323; Alternate Manufacturer: None; Manufacturer: Infineon Technologies; Value: -20V; Rdson45_ohm: 1.2; SizeX_mm: 2.2; AEC Category: Q101; ChMode: Enhancement; Vgs_V: -12V; Value1: 1; IdsMax_A: -390mA; ChType: P; SizeAreaWB_mm2: 10.24; QgTyp_nC: -0.5; SizeArea_mm2: 4.84; SizeZ_mm: 1.1
Q4 = CMP-0087214-1: N-Channel 600V 6.8A (Tc) 5W (Tc) Surface Mount PG-SOT223; Manufacturer: Infineon Technologies; VdsMax_V: 650V; SizeZ_mm: 1.8mm; Vgs_V: 20V; Rdson45_ohm: 0.9; ChMode: False; QgTyp_nC: 13nC @ 10V; AEC Qualified: No
Q5 = CMP-0067574-2: MOSFET, N-CH, Depletion Mode, 100 V, 0.17 A, AEC-Q101, SOT-23; Alternate Manufacturer: None; Manufacturer: Infineon Technologies; QgTyp_nC: 1.4; SizeAreaWB_mm2: 14.0; Vgs_V: 20V; Value1: ? ohm; VdsMax_V: 600V; Value: 600V; IdsMax_A: 21mA; SizeZ_mm: 1.1; SizeX_mm: 2.5; SizeY_mm: 3.0; Value2: 1.4 nC; SizeArea_mm2: 7.5; ChType: N; AEC Qualified: Y; AEC Category: Q101
Q6 = CMP-0000755-1: MOSFET, N-CH, 50 V, 0.22 A, SOT-23; Alternate Manufacturer: None; Manufacturer: Fairchild Semiconductor; SizeZ_mm: 1.1; ChType: N; Value2: 1.7 nC; VdsMax_V: 50V; SizeX_mm: 2.5; SizeY_mm: 3; Vgs_V: 20V; Value: 50V; Rdson45_ohm: 6; SizeArea_mm2: 7.5; AEC Category: Q101; IdsMax_A: 220mA; SizeAreaWB_mm2: 14; U/M: EA; QgTyp_nC: 1.7
Q7 Q101 = CMP-0000774-1: MOSFET, N-CH, 60 V, 0.31 A, SOT-323; Alternate Manufacturer: None; Manufacturer: Fairchild Semiconductor; SizeZ_mm: 1.1; ChType: N; Value1: 1; VdsMax_V: 60V; SizeX_mm: 2.2; Vgs_V: 2.1V; Value: 60V; Rdson45_ohm: 1.6; SizeArea_mm2: 4.84; AEC Category: Q101; IdsMax_A: 3.1dA; SizeAreaWB_mm2: 10.24; U/M: EA
R1 = CMP-0020501-3: RES, 22, 5%, 0.125 W, AEC-Q200 Grade 0, 0805; Manufacturer: Vishay-Dale; Power_W: 125mW; TempCo: 200 ppm/C; Value_Code: 22R0; Value: 22; EIA_Code: E24; SizeX_mm: 2; SizeY_mm: 1.25; SizeZ_mm: 1.45; Value2: 0.125W; SizeArea_mm2: 2.5; AEC Qualified: Y; VDC_V: 150V; AEC Category: Q200; AEC Grade: 0
R2 = CMP-0026403-2: RES, 49.9 k, 1%, 0.063 W, AEC-Q200 Grade 0, 0402; Manufacturer: Vishay-Dale; Power_W: 63mW; TempCo: 100 ppm/C; Value_Code: 49k9; Value: 49.9k; EIA_Code: E96; SizeX_mm: 1; SizeY_mm: 0.5; SizeZ_mm: 0.6; Value2: 0.063W; AEC Qualified: Y; VDC_V: 50V; AEC Category: Q200; AEC Grade: 0
R3 R16 = CMP-0026281-2: RES, 301, 1%, 0.063 W, AEC-Q200 Grade 0, 0402; Manufacturer: Vishay-Dale; Power_W: 63mW; TempCo: 100 ppm/C; Value_Code: 301R; Value: 301; EIA_Code: E96; SizeX_mm: 1; SizeY_mm: 0.5; SizeZ_mm: 0.6; Value2: 0.063W; AEC Qualified: Y; VDC_V: 50V; AEC Category: Q200; AEC Grade: 0
R4 = CMP-0026942-3: RES, 4.7, 5%, 0.063 W, AEC-Q200 Grade 0, 0402; Manufacturer: Vishay-Dale; Power_W: 63mW; TempCo: 200 ppm/C; Value_Code: 4R70; Value: 4.7; EIA_Code: E24; SizeX_mm: 1; SizeY_mm: 0.5; SizeZ_mm: 0.6; Value2: 0.063W; AEC Qualified: Y; VDC_V: 50V; AEC Category: Q200; AEC Grade: 0
R6 = CMP-0026543-2: RES, 75.0 k, 1%, 0.063 W, AEC-Q200 Grade 0, 0402; Manufacturer: Vishay-Dale; Power_W: 63mW; TempCo: 100 ppm/C; Value_Code: 75k0; Value: 75.0k; EIA_Code: E96; Res_ohm: 75k; SizeX_mm: 1; SizeY_mm: 0.5; SizeZ_mm: 0.6; Value2: 0.063W; AEC Qualified: Y; VDC_V: 50V; AEC Category: Q200; AEC Grade: 0
R8 R15 = CMP-0026669-1: RES, 150 k, 1%, 0.1 W, AEC-Q200 Grade 0, 0402; Manufacturer: Panasonic; Power_W: 100mW; TempCo: 100 ppm/C; U/M: EA; Value: 150k; EIA_Code: E96; SizeX_mm: 1; SizeY_mm: 0.5; SizeZ_mm: 0.6; Value2: 0.1W; CompType: Resistor; AEC Qualified: Y; VDC_V: 50V; AEC Grade: 0; AEC Category: Q200
R9 = CMP-0026730-1: RES, 30.1 k, 1%, 0.063 W, 0402; Manufacturer: Yageo America; Power_W: 63mW; TempCo: 100 ppm/C; Value_Code: 30k1; U/M: EA; Value: 30.1k; EIA_Code: E96; SizeX_mm: 1; SizeY_mm: 0.5; SizeZ_mm: 0.6; Value2: 0.063W; CompType: Resistor; AEC Qualified: N; VDC_V: 50V; AEC Category: Q200
R10 = CMP-0078669-1: RES, 10.0 k, 1%, 0.063 W, 0402; Manufacturer: Yageo America; Power_W: 63mW; Green_Lifecycle: Active; TempCo: 100 ppm/C; Value_Code: 10k0; Green_REACh: Passed; Value: 10.0k; EIA_Code: E96; Res_ohm: 10k; SizeX_mm: 1; SizeY_mm: 0.5; SizeZ_mm: 0.6; Value2: 0.063W; CompType: Resistor; AEC Qualified: N; AEC Category: Q200
R11 = CMP-0026727-1: RES, 1.00 M, 1%, 0.063 W, 0402; Manufacturer: Yageo America; Power_W: 63mW; TempCo: 100 ppm/C; Value_Code: 1M00; U/M: EA; Value: 1.00Meg; EIA_Code: E96; Res_ohm: 1M; SizeX_mm: 1; SizeY_mm: 0.5; SizeZ_mm: 0.6; Value2: 0.063W; CompType: Resistor; AEC Category: Q200
R12 = CMP-0025985-3: RES, 121, 1%, 0.063 W, AEC-Q200 Grade 0, 0402; Manufacturer: Vishay-Dale; Power_W: 63mW; TempCo: 100 ppm/C; Value_Code: 121R; Value: 121; EIA_Code: E96; SizeX_mm: 1; SizeY_mm: 0.5; SizeZ_mm: 0.6; Value2: 0.063W; AEC Qualified: Y; VDC_V: 50V; AEC Category: Q200; AEC Grade: 0
R13 R14 R20 = CMP-0026100-2: RES, 1.00 M, 1%, 0.063 W, AEC-Q200 Grade 0, 0402; Manufacturer: Vishay-Dale; Power_W: 63mW; TempCo: 100 ppm/C; Value_Code: 1M00; Value: 1.00Meg; EIA_Code: E96; Res_ohm: 1M; SizeX_mm: 1; SizeY_mm: 0.5; SizeZ_mm: 0.6; Value2: 0.063W; AEC Qualified: Y; VDC_V: 50V; AEC Category: Q200; AEC Grade: 0
R17 R25 R100 = CMP-0026435-2: RES, 511 k, 1%, 0.063 W, AEC-Q200 Grade 0, 0402; Manufacturer: Vishay-Dale; Power_W: 63mW; TempCo: 100 ppm/C; Value: 511k; EIA_Code: E96; SizeX_mm: 1; SizeY_mm: 0.5; SizeZ_mm: 0.6; Value2: 0.063W; CompType: Resistor; AEC Qualified: Y; VDC_V: 50V; AEC Category: Q200; AEC Grade: 0
R18 R23 = CMP-0026071-3: RES, 1.00 k, 1%, 0.063 W, AEC-Q200 Grade 0, 0402; Manufacturer: Vishay-Dale; Power_W: 63mW; TempCo: 100 ppm/C; Value_Code: 1k00; Value: 1.00k; EIA_Code: E96; Res_ohm: 1k; SizeX_mm: 1; SizeY_mm: 0.5; SizeZ_mm: 0.6; Value2: 0.063W; CompType: Resistor; AEC Qualified: Y; VDC_V: 50V; AEC Category: Q200; AEC Grade: 0
R19 = CMP-0026329-2: RES, 3.01 k, 1%, 0.063 W, AEC-Q200 Grade 0, 0402; Manufacturer: Vishay-Dale; Power_W: 63mW; TempCo: 100 ppm/C; Value_Code: 3k01; Value: 3.01k; EIA_Code: E96; SizeX_mm: 1; SizeY_mm: 0.5; SizeZ_mm: 0.6; Value2: 0.063W; AEC Qualified: Y; VDC_V: 50V; AEC Category: Q200; AEC Grade: 0
R21 = CMP-0026162-2: RES, 20.0 k, 1%, 0.063 W, AEC-Q200 Grade 0, 0402; Manufacturer: Vishay-Dale; Power_W: 63mW; TempCo: 100 ppm/C; Value_Code: 20k0; Value: 20.0k; EIA_Code: E96; Res_ohm: 20k; SizeX_mm: 1; SizeY_mm: 0.5; SizeZ_mm: 0.6; Value2: 0.063W; AEC Qualified: Y; VDC_V: 50V; AEC Category: Q200; AEC Grade: 0
R22 = CMP-0017277-2: RES, 0.15, 1%, 0.5 W, 1206; Manufacturer: Panasonic; Power_W: 500mW; TempCo: 250 ppm/C; Value_Code: R150; U/M: EA; Value: 0.15; EIA_Code: E96; Res_ohm: 1.5d; SizeX_mm: 3.2; SizeY_mm: 1.6; SizeZ_mm: 1.35; Value2: 0.5W; SizeArea_mm2: 5.12; CompType: Resistor; AEC Qualified: N; AEC Category: Q200
R24 R36 = CMP-0026304-2: RES, 34.0 k, 1%, 0.063 W, AEC-Q200 Grade 0, 0402; Manufacturer: Vishay-Dale; Power_W: 63mW; TempCo: 100 ppm/C; Value_Code: 34k0; Value: 34.0k; EIA_Code: E96; Res_ohm: 34k; SizeX_mm: 1; SizeY_mm: 0.5; SizeZ_mm: 0.6; Value2: 0.063W; CompType: Resistor; AEC Qualified: Y; VDC_V: 50V; AEC Category: Q200; AEC Grade: 0
R26 = CMP-0026321-2: RES, 392 k, 1%, 0.063 W, AEC-Q200 Grade 0, 0402; Manufacturer: Vishay-Dale; PartNumber: CRCW0402393KFKED; Power_W: 63mW; TempCo: 100 ppm/C; Value: 392k; EIA_Code: E96; Res_ohm: 383k; SizeX_mm: 1; SizeY_mm: 0.5; SizeZ_mm: 0.6; Value2: 0.063W; AEC Qualified: Y; VDC_V: 50V; AEC Category: Q200; AEC Grade: 0
R28 = CMP-0026574-2: RES, 82.5 k, 1%, 0.063 W, AEC-Q200 Grade 0, 0402; Manufacturer: Vishay-Dale; Power_W: 63mW; TempCo: 100 ppm/C; Value_Code: 82k5; Value: 82.5k; EIA_Code: E96; SizeX_mm: 1; SizeY_mm: 0.5; SizeZ_mm: 0.6; Value2: 0.063W; CompType: Resistor; AEC Qualified: Y; VDC_V: 50V; AEC Grade: 0; AEC Category: Q200
R32 = CMP-0026063-3: RES, 191 k, 1%, 0.063 W, AEC-Q200 Grade 0, 0402; Manufacturer: Vishay-Dale; Power_W: 63mW; TempCo: 100 ppm/C; Value: 191k; EIA_Code: E96; SizeX_mm: 1; SizeY_mm: 0.5; SizeZ_mm: 0.6; Value2: 0.063W; CompType: Resistor; AEC Qualified: Y; VDC_V: 50V; AEC Category: Q200; AEC Grade: 0
R37 = CMP-0026510-2: RES, 69.8 k, 1%, 0.063 W, AEC-Q200 Grade 0, 0402; Manufacturer: Vishay-Dale; Power_W: 63mW; TempCo: 100 ppm/C; Value_Code: 69k8; Value: 69.8k; EIA_Code: E96; SizeX_mm: 1; SizeY_mm: 0.5; SizeZ_mm: 0.6; Value2: 0.063W; CompType: Resistor; AEC Qualified: Y; VDC_V: 50V; AEC Category: Q200; AEC Grade: 0
R38 = CMP-0026658-1: RES, 10.0 k, 1%, 0.1 W, 0402; Manufacturer: Panasonic; Power_W: 100mW; TempCo: 100 ppm/C; Value_Code: 10k0; U/M: EA; Value: 10.0k; EIA_Code: E96; Res_ohm: 10k; SizeX_mm: 1; SizeY_mm: 0.5; SizeZ_mm: 0.6; Value2: 0.1W; CompType: Resistor; VDC_V: 50V; AEC Category: Q200
R200 = CMP-0026555-2: RES, 7.50 k, 1%, 0.063 W, AEC-Q200 Grade 0, 0402; Manufacturer: Vishay-Dale; Power_W: 63mW; TempCo: 100 ppm/C; Value_Code: 7k50; Value: 7.50k; EIA_Code: E96; Res_ohm: 7.5k; SizeX_mm: 1; SizeY_mm: 0.5; SizeZ_mm: 0.6; Value2: 0.063W; AEC Qualified: Y; VDC_V: 50V; AEC Category: Q200; AEC Grade: 0
RT1 = CMP-0002523-3: Thermistor NTC, 47k ohm, 5%, 0603; Manufacturer: MuRata; TaMax_C: 125°C; SizeX_mm: 1.6; SizeY_mm: 0.8; TaMin_C: -40°C; Power_W: 100mW; SizeZ_mm: 1; SizeArea_mm2: 1.28; SizeAreaWB_mm2: 4.68; U/M: EA
T1 = CMP-0086869-1: Transformer; Manufacturer: Würth Elektronik; AEC Qualified: No; Rsec1_ohm: 8m; SizeZ_mm: 17.32mm; DCR_ohm: 0.05; Ns1toNp: 5.5:1/3.14:1/4.4:1; Ind_H: 75µH
U1 = CMP-0086802-1: FAST TURN-OFF INTELLIGENT RECTIF; Manufacturer: Monolithic Power Systems; SizeZ_mm: 1mm
U2 = CMP-0077706-1: 3-kVRMS Single-Channel Isolated Gate Drivers, D0008B (SOIC-8); Alternate Manufacturer: Texas Instruments; SizeAreaWB_mm2: 55.2; SizeZ_mm: 1.75; SizeX_mm: 6.0; SizeY_mm: 4.9; SizeArea_mm2: 29.4; CompType: IC; AEC Qualified: N; AEC Category: Q200
U3 = CMP-0078736-2: 600-V 12-A Single Channel GaN Power Stage, RWH0032A (VQFN-32); Manufacturer: Texas Instruments; AEC Qualified: N; SizeAreaWB_mm2: 100; SizeX_mm: 8; AEC Category: Q200; SizeZ_mm: 0.9; SizeArea_mm2: 64; CompType: IC
U4 = CMP-0085889-2: Small-Size Micropower Low-Voltage Comparator, DCK0005A (SOT-SC70-5); Manufacturer: Texas Instruments; Alternate PartNumber: TLV7021DCKT; SizeAreaWB_mm2: 9.3; SizeY_mm: 2; Rating: Catalog; SizeZ_mm: 1.1; SizeX_mm: 2.1; CompType: IC; AEC Qualified: N; SizeArea_mm2: 4.2; AEC Category: Q200
U5 = CMP-0006160-3: Optocoupler, 5 kV, 100-200% CTR, SMT; Manufacturer: Vishay-Semiconductor; CTR (Max): 125%; SizeAreaWB_mm2: 74.42; CTR (Min): 63%; SizeZ_mm: 2.3; SizeX_mm: 10.2; SizeY_mm: 4.1; SizeArea_mm2: 41.82; Voltage_Isolation_Vrms: 5kV
U6 = CMP-0014005-4: Active-Clamp Flyback Controller, RTE0016C (WQFN-16); Manufacturer: Texas Instruments; SizeZ_mm: 0.8; SizeX_mm: 3; SizeArea_mm2: 9; CompType: IC; U/M: EA; SizeAreaWB_mm2: 16

## Sheet PMP21639_REVD2_pg2.SchDoc
size 431 x 279 mm; Date: Not shown in title block; ApprovedBy: Not shown in title block; CheckedBy: Not shown in title block; Author: Ryan Tan; CompanyName: Not shown in title block; Engineer: Not shown in title block; Organization: Not shown in title block; Address1: Not shown in title block; Address2: Not shown in title block; Address3: Not shown in title block; Address4: Not shown in title block; DocumentNumber: 2; Revision: Use project parameter SCH_Rev; SheetNumber: 2; SheetTotal: 2; PageSetup: Record=PageOptions¦CenterHorizontal=True¦CenterVertical=True¦PrintScale=1.00¦XCorrection=1.00¦YCorrection=1.00¦PrintKind=0¦BorderSize=5000000¦LeftOffset=0¦BottomOffset=0¦Orientation=2¦PaperLength=1000¦PaperWidth=1000¦Scale=100¦PaperSource=15¦PrintQuality=600¦MediaType=1¦DitherType=10¦PaperKind=Letter¦PrintScaleMode=1
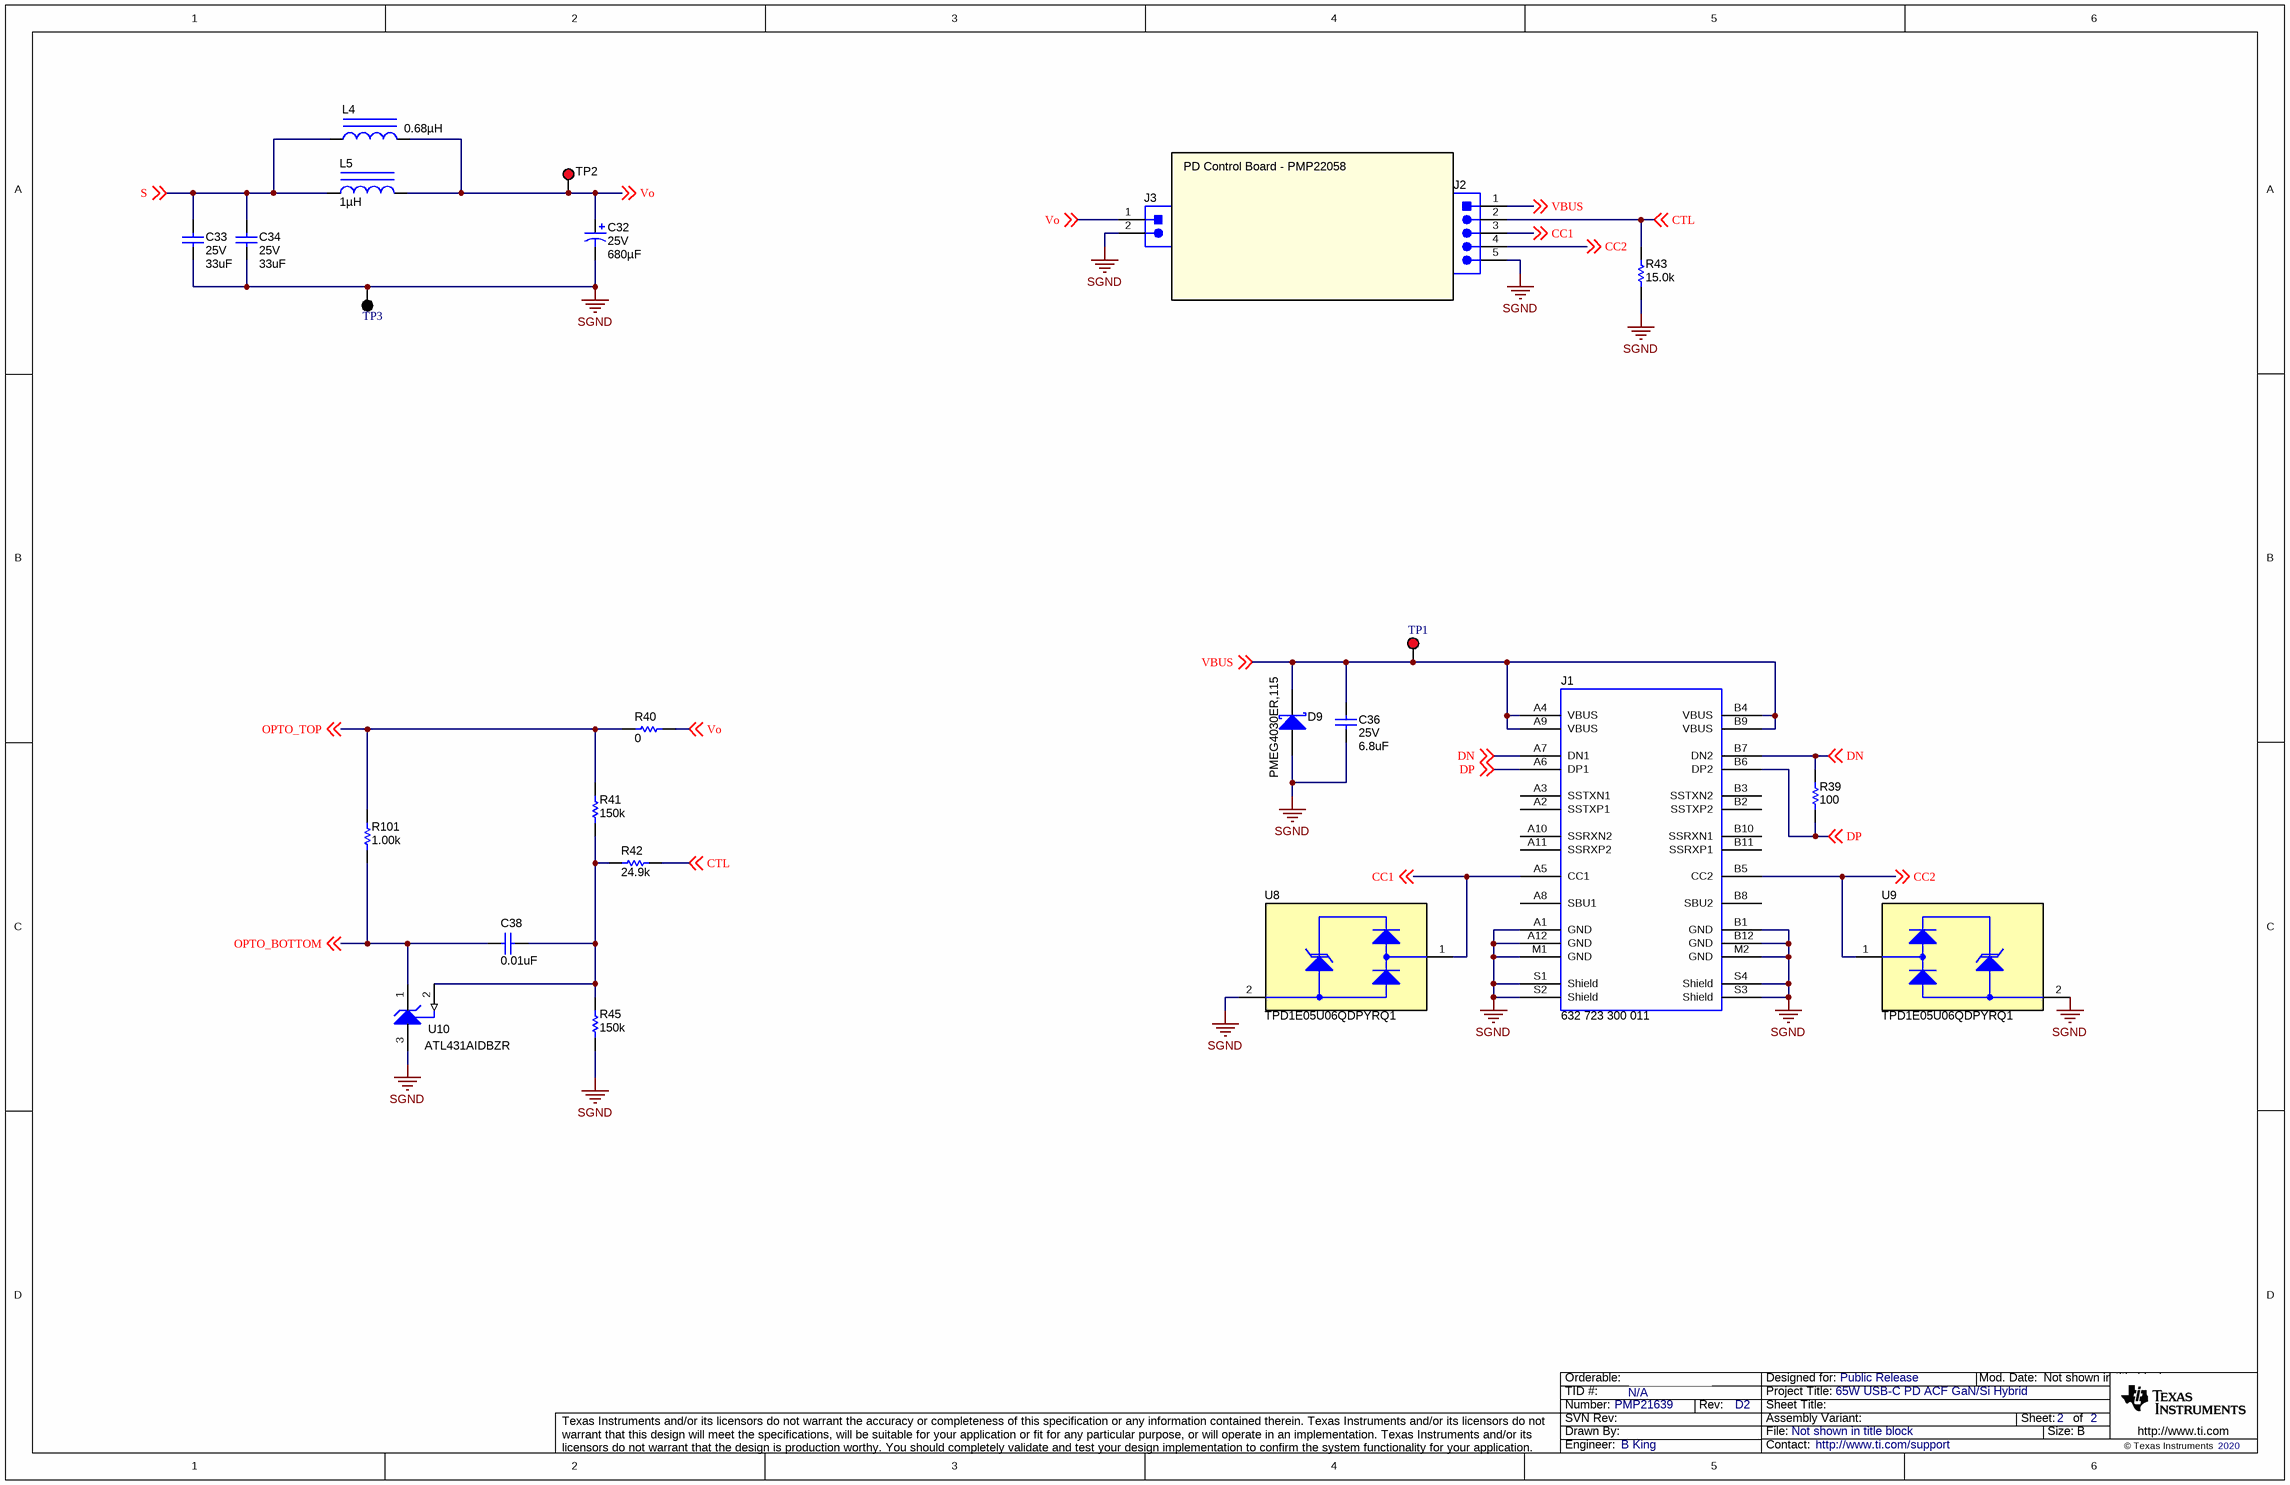
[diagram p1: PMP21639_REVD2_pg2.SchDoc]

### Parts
C32  VDC_V: 25V  ValueDisplayed: 680µF  [AVG_1000x1200_HU]  (hidden comment: 687AVG025MGBJ)
C33  VDC_V: 25V  ValueDisplayed: 33uF  [1206_180L]  (hidden comment: C3216X5R1E336M160AC)
C34  VDC_V: 25V  ValueDisplayed: 33uF  [1206_180L]  (hidden comment: C3216X5R1E336M160AC)
C36  VDC_V: 25V  ValueDisplayed: 6.8uF  [0805L]  (hidden comment: C2012X5R1E685K125AC)
C38  ValueDisplayed: 0.01uF  [0402S]  (hidden comment: GRM155R71E103KA01D)
D9  PMEG4030ER,115  [SOD-123W]
J1  632 723 300 011  [Wurth_632_723_300_011]
J2  GRPB051VWVN-RC  [Sullins_GRPB051VWVN-RC]  (value not drawn)
J3  GRPB021VWVN-RC  [Sullins_GRPB021VWVN-RC]  (value not drawn)
L4  ValueDisplayed: 0.68µH  [1206L]  (hidden comment: 74479136)
L5  ValueDisplayed: 1µH  [WE-HCI_5040]  (hidden comment: 744316100)
R39  ValueDisplayed: 100  [0402S]  (hidden comment: CRCW0402100RFKED)
R40  ValueDisplayed: 0  [0402S]  (hidden comment: RC0402JR-070RL)
R41  ValueDisplayed: 150k  [0402S]  (hidden comment: ERJ-2RKF1503X)
R42  ValueDisplayed: 24.9k  [0402S]  (hidden comment: CRCW040224K9FKED)
R43  ValueDisplayed: 15.0k  [0402L]  (hidden comment: CRCW040215K0FKED)
R45  ValueDisplayed: 150k  [0402S]  (hidden comment: ERJ-2RKF1503X)
R101  ValueDisplayed: 1.00k  [0805_HV]  (hidden comment: CRCW08051K00FKEA)
TP1  5000  [Keystone5000]  (value not drawn)
TP2  Vout  [Keystone5010]  (value not drawn)
TP3  5001  [Keystone5001]  (value not drawn)
U8  TPD1E05U06QDPYRQ1  [DPY0002A]
U9  TPD1E05U06QDPYRQ1  [DPY0002A]
U10  ATL431AIDBZR  [DBZ0003A_L]

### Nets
SGND: C32.2(-) C33.2 C34.2 C36.2 D9.2(A) J1.A1(GND) J1.A12(GND) J1.B1(GND) J1.B12(GND) J1.M1(GND) J1.M2(GND) J1.S1(Shield) J1.S2(Shield) J1.S3(Shield) J1.S4(Shield) J2.5 J3.2 R43.1 R45.2 TP3.1 U8.2(GND) U9.2(GND) U10.3(ANODE)
CC1: J1.A5(CC1) J2.3 U8.1(I/O) ; off-sheet CC1
CC2: J1.B5(CC2) J2.4 U9.1(I/O) ; off-sheet CC2
CTL: J2.2 R42.1 R43.2 ; off-sheet CTL
DN: J1.A7(DN1) J1.B7(DN2) R39.2 ; off-sheet DN
DP: J1.A6(DP1) J1.B6(DP2) R39.1 ; off-sheet DP
OPTO_BOTTOM: C38.2 R101.1 U10.1(CATHODE) ; off-sheet OPTO_BOTTOM
OPTO_TOP: R40.1 R41.2 R101.2 ; off-sheet OPTO_TOP
S: C33.1 C34.1 L4.1 L5.1 ; off-sheet S
VBUS: C36.1 D9.1(K) J1.A4(VBUS) J1.A9(VBUS) J1.B4(VBUS) J1.B9(VBUS) J2.1 TP1.1 ; off-sheet VBUS
Vo: C32.1(+) J3.1 L4.2 L5.2 R40.2 TP2.1 ; off-sheet Vo
NetC38_1: C38.1 R41.1 R42.2 R45.1 U10.2(REF)

Not connected (* = marked no-connect by the designer): J1 A2(SSTXP1) A3(SSTXN1) A8(SBU1) A10(SSRXN2) A11(SSRXP2) B2(SSTXP2) B3(SSTXN2) B8(SBU2) B10(SSRXN1) B11(SSRXP1)

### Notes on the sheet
- PD Control Board - PMP22058

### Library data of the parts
C32 = CMP-0081668-2: CAP, Aluminum Polymer, 680 µF, 25 V,+/- 20%, 0.29256 ohm, TH; Manufacturer: Illinois Capacitor; CompType: Capacitor; Cap_Case: 10x12mm; AEC Qualified: N; AEC Category: Q200; SizeArea_mm2: 100; SizeAreaWB_mm2: 144; Polarized: Y; SizeZ_mm: 13.5; SizeX_mm: 10; TaMax_C: 125°C; Value: 680uF; IRMS_A: 4.7A; TaMin_C: -55°C
C33 C34 = CMP-0008655-2: as C8 on sheet PMP21639_REVD2_pg1
C36 = CMP-0007830-2: CAP, CERM, 6.8 uF, 25 V, +/- 10%, X5R, 0805; Manufacturer: TDK; TaMin_C: -55°C; Polarized: N; SizeAreaWB_mm2: 6.75; Value1: Unknown; U/M: EA; Value: 6.8uF; TaMax_C: 85°C; SizeZ_mm: 1.45; SizeX_mm: 2; Cap_Case: 0805; SizeArea_mm2: 2.5; CompType: Capacitor; Cap_F: 6.8µF; AEC Category: Q200; SizeY_mm: 1.25
C38 = CMP-0006658-2: as C15 on sheet PMP21639_REVD2_pg1
D9 = CMP-0080763-2: Diode, Schottky, 40 V, 3 A, AEC-Q101, SOD-123W; Manufacturer: Nexperia; Value2: 0.54V; AEC Category: Q101; SizeArea_mm2: 5.95; AEC Qualified: Y; Io_A: 3A; SizeZ_mm: 1; Value: 40V; SizeY_mm: 1.7; Vf_V: 540mV; SizeAreaWB_mm2: 12.15; SizeX_mm: 3.5; TJmax_C: 150°C
J1 = CMP-0054818-1: Connector, Receptacle, USB Type C, R/A; Manufacturer: Wurth Elektronik; CNHeader: FALSE; Current_A: 3A; Gender: Female; Voltage_V: 5V; ContactFinish: Gold; CT: TRUE; Cert_UL: Y
J2 = CMP-0054560-1: Header, 50mil, 5x1, Gold, TH; Manufacturer: Sullins Connector Solutions; CT: FALSE; CNHeader: TRUE
J3 = CMP-0054555-1: Header, 50mil, 2x1, Gold, TH; Manufacturer: Sullins Connector Solutions; CNHeader: TRUE; Green_Lifecycle: Not Set; Green_REACh: Incomplete; CT: FALSE
L4 = 744042330: Inductor, 1206, 0.68uH, 0.15 A, SMD; Manufacturer: Wurth Elektronik; Ind_H: 33.0E-6; Imax_A: 0.5; Irms: 0.72A @ 30C rise; Isat: 0.5A @ 35% inductance drop; DCR_ohm: 0.382; Value1: 0.382 ohm; Value2: 0.5A; Material: Metal Composite; SizeAreaWB_mm2: 33.64; SizeArea_mm2: 23.04; SizeX_mm: 4.8; SizeZ_mm: 2; AEC Category: Q200
L5 = CMP-0080751-1: Inductor, Shielded, 1 µH, 11.5 A, 5.225 ohm, SMD; Manufacturer: Wurth Elektronik; SizeAreaWB_mm2: 55.48; Irms: 11.5A @ 50C rise; SizeArea_mm2: 29.68; AEC Qualified: N; AEC Category: Q200; Value: 1uH; SizeZ_mm: 4.3; Imax_A: 11.5A; SizeY_mm: 5.3; Isat: 11.5A @ 30% inductance drop; DCR_ohm: 5.225; SizeX_mm: 5.6
R39 = CMP-0025951-3: RES, 100, 1%, 0.063 W, AEC-Q200 Grade 0, 0402; Manufacturer: Vishay-Dale; Power_W: 63mW; TempCo: 100 ppm/C; Value_Code: 100R; Value: 100; EIA_Code: E96; SizeX_mm: 1; SizeY_mm: 0.5; SizeZ_mm: 0.6; Value2: 0.063W; CompType: Resistor; AEC Qualified: Y; VDC_V: 50V; AEC Category: Q200; AEC Grade: 0
R40 = CMP-0027004-2: RES, 0, 5%, 0.063 W, 0402; Manufacturer: Yageo America; Power_W: 63mW; TempCo: 200 ppm/C; Value_Code: 0000; U/M: EA; Value: 0; EIA_Code: E24; SizeX_mm: 1; SizeY_mm: 0.5; SizeZ_mm: 0.6; Value2: 0.063W; CompType: Resistor; VDC_V: 50V; AEC Category: Q200
R41 R45 = CMP-0026669-1: as R8 on sheet PMP21639_REVD2_pg1
R42 = CMP-0026196-2: RES, 24.9 k, 1%, 0.063 W, AEC-Q200 Grade 0, 0402; Manufacturer: Vishay-Dale; Power_W: 63mW; TempCo: 100 ppm/C; Value_Code: 24k9; Value: 24.9k; EIA_Code: E96; SizeX_mm: 1; SizeY_mm: 0.5; SizeZ_mm: 0.6; Value2: 0.063W; CompType: Resistor; AEC Qualified: Y; VDC_V: 50V; AEC Category: Q200; AEC Grade: 0
R43 = CMP-0026027-3: RES, 15.0 k, 1%, 0.063 W, AEC-Q200 Grade 0, 0402; Manufacturer: Vishay-Dale; Power_W: 63mW; TempCo: 100 ppm/C; Value_Code: 15k0; Value: 15.0k; EIA_Code: E96; Res_ohm: 15k; SizeX_mm: 1; SizeY_mm: 0.5; SizeZ_mm: 0.6; Value2: 0.063W; AEC Qualified: Y; VDC_V: 50V; AEC Category: Q200; AEC Grade: 0
R101 = CMP-0020951-3: RES, 1.00 k, 1%, 0.125 W, AEC-Q200 Grade 0, 0805; Manufacturer: Vishay-Dale; Power_W: 125mW; TempCo: 100 ppm/C; Value_Code: 1k00; Value: 1.00k; EIA_Code: E96; Res_ohm: 1k; SizeX_mm: 2; SizeY_mm: 1.25; SizeZ_mm: 1.45; Value2: 0.125W; SizeArea_mm2: 2.5; AEC Qualified: Y; VDC_V: 150V; AEC Category: Q200; AEC Grade: 0
TP1 = CMP-0055137-1: Test Point, Miniature, Red, TH; Manufacturer: Keystone; CNHeader: FALSE; Green_Lifecycle: Active; Green_REACh: Passed; ContactFinish: Silver; CT: TRUE
TP2 = CMP-0055147-1: Test Point, Multipurpose, Red, TH; PartNumber: 5010; Manufacturer: Keystone; ContactFinish: Silver; CNHeader: FALSE; CT: TRUE; Green_Lifecycle: Active; Green_REACh: Passed
TP3 = CMP-0055138-1: Test Point, Miniature, Black, TH; Manufacturer: Keystone; CNHeader: FALSE; Green_Lifecycle: Active; Green_REACh: Passed; ContactFinish: Silver; CT: TRUE
U8 U9 = CMP-0073591-3: Automotive 1-Channel Ultra-Low-Capacitance IEC ESD Protection Diode, DPY0002A (X1SON-2); Alternate PartNumber: TPD1E05U06QDPYTQ1; Alternate Manufacturer: Texas Instruments; SizeZ_mm: 0.45; SizeY_mm: 0.6; AEC Qualified: Y; SizeAreaWB_mm2: 3.2; SizeX_mm: 1.0; AEC Category: Q200; CompType: IC
U10 = CMP-0066199-1: 2.5V Low Iq Adjustable Precision Shunt Regulator, DBZ0003A (SOT-23-3); Manufacturer: Texas Instruments; SizeArea_mm2: 7.5; SizeAreaWB_mm2: 14.0; SizeX_mm: 2.5; SizeY_mm: 3.0; SizeZ_mm: 1.12; CompType: IC; U/M: EA

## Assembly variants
001: not fitted C28 C34 C37 D3 J2 J3 R27 R29 R30 R31 R33 R34 R35 R43 R44 R46 RT1 U7 U11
